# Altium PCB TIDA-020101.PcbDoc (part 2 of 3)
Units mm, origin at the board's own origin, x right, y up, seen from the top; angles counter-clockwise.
Board outline 55 x 55 mm, 4 copper layers (Top Layer 1, Top Layer, Bottom Layer, Bottom Layer 1), stack 1.647 mm thick; 151 components, 88 nets, 395 pads, 362 vias.
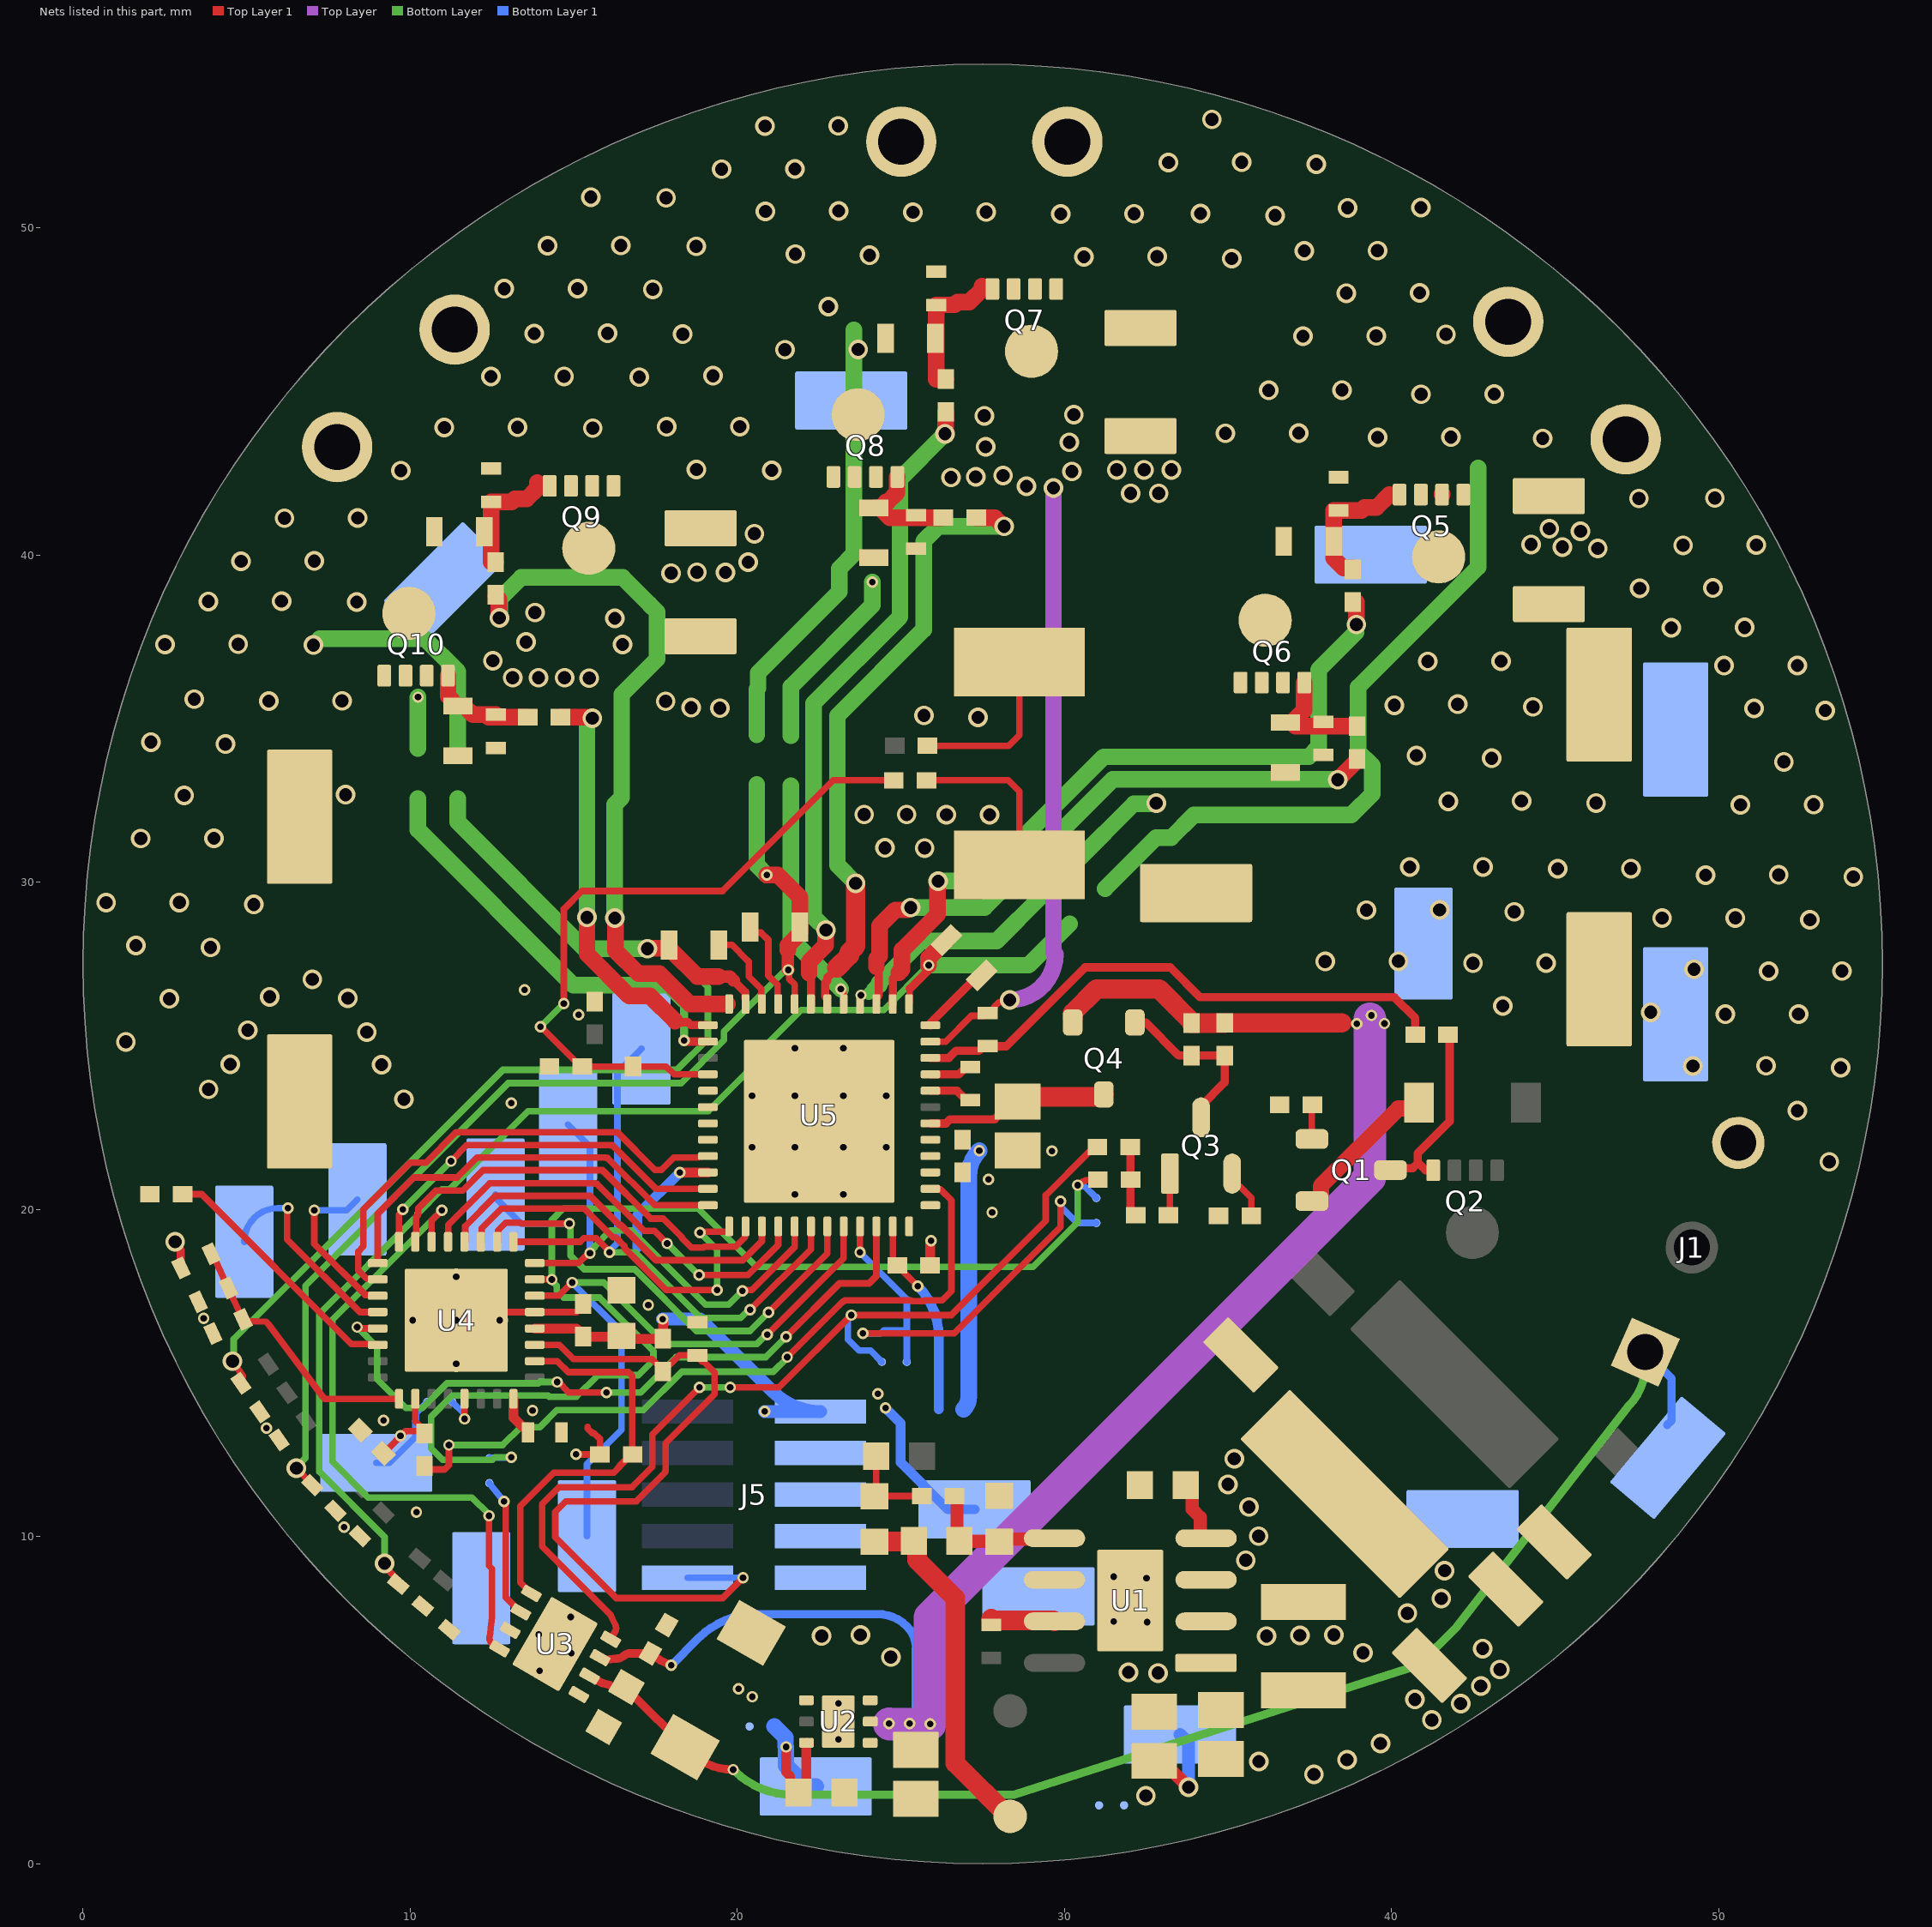
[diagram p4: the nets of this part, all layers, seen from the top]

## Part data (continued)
C13 C15 C22 C25: library part CMP-0080610-1, "CAP, CERM, 0.1 µF, 25 V,+/- 10%, X7R, AEC-Q200 Grade 1, 0402", Cap_Case=0402, Manufacturer=TDK, Supplier Part Number 1=445-6902-1-ND, TempCo=X7R, Tolerance_%=10%, Value2=25V, ValueDisplayed=0.1µF
C14: library part CMP-0007003-5, "CAP, CERM, 10 uF, 10 V, +/- 20%, X5R, 0603", Cap_Case=0603, Manufacturer=TDK, Supplier Part Number 1=445-6853-1-ND, TempCo=X5R, Tolerance_%=20%, Value1="0.0078 ohm", Value2=10V, ValueDisplayed=10uF
C16: library part CMP-0860964-1, "CAP, CERM, 0.47 µF, 16 V,+/- 10%, X7S, 0402", Cap_Case=0402, Manufacturer=TDK, TempCo=X7S, Tolerance_%=10%, Value2=16V, ValueDisplayed=0.47µF
C17 C18 C19 C20 C21: library part CMP-0006639-2, "CAP, CERM, 0.01 uF, 16 V, +/- 10%, X7R, 0402", Cap_Case=0402, Manufacturer=MuRata, Supplier Part Number 1=490-1313-1-ND, TempCo=X7R, Tolerance_%=10%, Value1=Unknown, Value2=16V, ValueDisplayed=0.01uF
C24: library part CMP-0006320-2, "CAP, CERM, 470 pF, 50 V, +/- 10%, X7R, AEC-Q200 Grade 1, 0402", Cap_Case=0402, Manufacturer=TDK, Supplier Part Number 1=445-6888-1-ND, TempCo=X7R, Tolerance_%=10%, Value1="4.96489 ohm", Value2=50V, ValueDisplayed=470pF
C26 C27 C31: library part CMP-0006276-2, "CAP, CERM, 1 uF, 25 V, +/- 10%, X5R, 0402", Cap_Case=0402, Manufacturer=TDK, Supplier Part Number 1=445-9066-1-ND, TempCo=X5R, Tolerance_%=10%, Value1=Unknown, Value2=25V, ValueDisplayed=1uF
C28 C29 C30: library part CMP-0082523-1, "CAP, CERM, 1 µF, 25 V,+/- 10%, X7R, AEC-Q200 Grade 1, 0603", Cap_Case=0603, Manufacturer=TDK, Supplier Part Number 1=445-9819-1-ND, TempCo=X7R, Tolerance_%=10%, Value2=25V, ValueDisplayed=1µF
C32 C33 C35: library part CMP-0127119-1, "130 µF 80 V Aluminum - Polymer Capacitors Radial, Can - SMD 16mOhm 4000 Hrs @ 125°C", Digikey Part Number=495-B40910A0137M000TR-ND, Leakage Current=100uA, Manufacturer=TDK, Mouser Part Number=871-B40910A0137M000, Operating Temperature Range="-55°C to +150°C", Tolerance_%=20%, ValueDisplayed=130uF
C36 C37 C38: library part CMP-0006332-2, "CAP, CERM, 1000 pF, 100 V, +/- 10%, X7S, AEC-Q200 Grade 1, 0402", Cap_Case=0402, Manufacturer=TDK, Supplier Part Number 1=445-6904-1-ND, TempCo=X7S, Tolerance_%=10%, Value1="2.71151 ohm", Value2=100V, ValueDisplayed=1000pF
C40 C41 C43 C44 C46 C47: library part CMP-0007082-4, "CAP, CERM, 0.01 uF, 100 V, +/- 10%, X7R, AEC-Q200 Grade 1, 0603", Cap_Case=0603, Manufacturer=TDK, Supplier Part Number 1=445-5812-1-ND, TempCo=X7R, Tolerance_%=10%, Value1="0.235428 ohm", Value2=100V, ValueDisplayed=0.01uF
D1: library part CMP-0080761-2, "Diode, Switching, 100 V, 0.25 A, AEC-Q101, SOD-123", Manufacturer=Vishay-Semiconductor, Value1=0.25A, Value2=1.25V
D2: library part CMP-0006043-3, "Diode, TVS, Bi, 58.1 V, 121 Vc, AEC-Q101, SMD, 2-Leads, Body 4.275x2.575mm", Manufacturer=STMicroelectronics, Value1=600W
J1: library part CMP-0055340-2, "Terminal Block, 3.5 mm, 3x1, Tin, TH", Manufacturer=Molex, Supplier Part Number 1=WM7878-ND
J2 J3 J4 J6 J7 J8 J9: library part CMP-0080367-2, "Solder Jumper, SMT", Manufacturer=NA
J5: library part CMP-0075634-2, "Header(Shrouded), 1.27mm, 5x2, Gold, SMT", Color=Black, Current_A=3.3A, Manufacturer=Samtec, Supplier Part Number 1=SAM8799-ND
L1: library part CMP-0126669-1, "2.2 µH Shielded Wirewound Inductor 12.4 A 11.9mOhm Max Nonstandard", Digikey Part Number=732-74438377022CT-ND, Manufacturer="Wurth Electronics", Mouser Part Number=710-74438377022, Operating Temperature Range="-40°C to +125°C", Self Resonant Frequency=30MHz, Test Frequency=100kHz, Tolerance_%=20%
L2: library part CMP-0123992-1, "Low Profile Shielded Power Inductors 100uH 20% 0.82A 0.475 Ohm", Manufacturer=Coilcraft, Operating Temperature Range=to, Self Resonant Frequency=8.6MHz, Test Frequency=100kHz, Tolerance_%=20%
Logo1: library part CMP-0074844-1
Logo2 Logo5: library part CMP-0074838-1, "Texas Instrument Corporate Signature"
Logo3: library part CMP-0074847-1, "FCC_disclaimer"
Logo4: library part CMP-0074769-1
Logo6: library part CMP-0074837-2, "IEC 61010-1 Hot Surface Warning", Manufacturer="Texas Instruments"
MH1 MH2 MH3: library part CMP-0089624-1, "0.250\" (6.35mm) Quick Connect Male  Solder Connector Non-Insulated", Current_A=20A, Digikey Part Number=A29938CT-ND, Manufacturer="TE Connectivity", Mouser Part Number=571-638241, Operating Temperature Range="-40°C to +105°C"
NT1 NT2 NT3 NT4 NT5 NT6 NT7: library part CMP-0078142-6, "Single point connection between nets.", Manufacturer=N/A
Q1: library part CMP-0000380-2, "Transistor, NPN, 32 V, 0.1 A, SOT-23", Manufacturer="Infineon Technologies", Supplier Part Number 1="BCW 60D E6327-ND", Value1="0.1 A", Value2=630
Q2 Q5 Q6 Q7 Q8 Q9 Q10: library part CMP-0126680-2, "N-Channel 80 V 11A (Ta), 68A (Tc) 3.2W (Ta), 107W (Tc) Surface Mount 8-WDFN (3.3x3.3)", Digikey Part Number=NVTFS6H850NTAGOSCT-ND, Drain To Source Breakdown Voltage=80V, Input Capacitace At Vds="1140pF @ 40V", Manufacturer=onsemi, Mouser Part Number=863-NVTFS6H850NTAG, Operating Temperature Range="-55°C to +175°C", Power_W=3.2W, Pulse Drain Current=300A, Typ Forward Diode Voltage=0.8V
Q3: library part CMP-0097440-1, "Bipolar (BJT) Transistor NPN 40 V 200 mA 300MHz 300 mW Surface Mount SOT-23-3 (TO-236)", Collector Base Voltage=60V, Digikey Part Number=SMMBT3904LT3GOSCT-ND, Emitter Base Voltage=6V, Manufacturer="On Semiconductor", Mouser Part Number=863-SMMBT3904LT3G, Operating Temperature Range="-55°C to +150°C", Power_W=225mW, Unity Gain Freq=300MHz
Q4: library part CMP-0000155-3, "MOSFET, P-CH, -60 V, -0.185 A, SOT-23", Alternate Manufacturer=None, Manufacturer=Vishay-Siliconix, Value1=1, Value2="1.7 nC"
R1 R10: library part CMP-0026935-3, "RES, 47 k, 5%, 0.063 W, AEC-Q200 Grade 0, 0402", Manufacturer=Vishay-Dale, Power_W=63mW, Supplier Part Number 1=541-47KJCT-ND, TempCo="200 ppm/C", Tolerance_%=5%, Value2=0.063W, Value_Code=47k0, ValueDisplayed=47k
R2 R7 R9 R19 R20 R22: library part CMP-0026825-5, "RES, 10 k, 5%, 0.063 W, AEC-Q200 Grade 0, 0402", Manufacturer=Vishay-Dale, Power_W=63mW, Supplier Part Number 1=541-10KJCT-ND, TempCo="200 ppm/C", Tolerance_%=5%, Value2=0.063W, Value_Code=10k0, ValueDisplayed=10k
R3: library part CMP-0022632-4, "RES, 88.7 k, 1%, 0.1 W, AEC-Q200 Grade 0, 0603", Manufacturer=Vishay-Dale, Power_W=100mW, Supplier Part Number 1=541-88.7KHCT-ND, TempCo="100 ppm/C", Tolerance_%=1%, Value2=0.1W, Value_Code=88k7, ValueDisplayed=88.7k
R4: library part CMP-0025319-2, "RES, 481 k, 0.5%, 0.1 W, 0603", Manufacturer="Yageo America", Power_W=100mW, TempCo="50 ppm/C", Tolerance_%=0.5%, Value2=0.1W, Value_Code=481k
R5: library part CMP-0023120-4, "RES, 453 k, 1%, 0.1 W, 0603", Manufacturer=Yageo, Power_W=100mW, Supplier Part Number 1=311-453KHRCT-ND, TempCo="100 ppm/C", Tolerance_%=1%, Value2=0.1W, Value_Code=453k
R6: library part CMP-0024307-2, "RES, 50.5 k, 0.1%, 0.1 W, 0603", Manufacturer="Yageo America", Power_W=100mW, TempCo="25 ppm/C", Tolerance_%=0.1%, Value2=0.1W, Value_Code=50k5, ValueDisplayed=50.5k
R8: library part CMP-0026938-5, "RES, 4.7 k, 5%, 0.063 W, AEC-Q200 Grade 0, 0402", Manufacturer=Vishay-Dale, Power_W=63mW, Supplier Part Number 1=541-4.7KJCT-ND, TempCo="200 ppm/C", Tolerance_%=5%, Value2=0.063W, Value_Code=4k70, ValueDisplayed=4.7k
R11 R13 R15 R17: library part CMP-0026615-3, "RES, 976 k, 1%, 0.063 W, AEC-Q200 Grade 0, 0402", Manufacturer=Vishay-Dale, Power_W=63mW, Supplier Part Number 1=541-976KLCT-ND, TempCo="100 ppm/C", Tolerance_%=1%, Value2=0.063W, Value_Code=976k
R12 R14 R16 R18: library part CMP-0026284-2, "RES, 30.1 k, 1%, 0.063 W, AEC-Q200 Grade 0, 0402", Manufacturer=Vishay-Dale, Power_W=63mW, Supplier Part Number 1=541-30.1KLCT-ND, TempCo="100 ppm/C", Tolerance_%=1%, Value2=0.063W, Value_Code=30k1, ValueDisplayed=30.1k
R21 R29 R31 R33 R35 R37 R39: library part CMP-0026823-3, "RES, 100 k, 5%, 0.063 W, AEC-Q200 Grade 0, 0402", Manufacturer=Vishay-Dale, Power_W=63mW, Supplier Part Number 1=541-100KJCT-ND, TempCo="200 ppm/C", Tolerance_%=5%, Value2=0.063W, Value_Code=100k
R24: library part CMP-0026845-3, "RES, 160, 5%, 0.063 W, AEC-Q200 Grade 0, 0402", Manufacturer=Vishay-Dale, Power_W=63mW, Supplier Part Number 1=541-160JCT-ND, TempCo="200 ppm/C", Tolerance_%=5%, Value2=0.063W, Value_Code=160R, ValueDisplayed=160
R25: library part CMP-0015751-2, "RES, 0.005, 1%, 3 W, AEC-Q200 Grade 0, 2512", Manufacturer=Bourns, Power_W=3W, Supplier Part Number 1=CRE2512-FZ-R005E-3CT-ND, TempCo="75 ppm/C", Tolerance_%=1%, Value_Code=5L000, ValueDisplayed=0.005
R26 R27: library part CMP-0025963-3, "RES, 10.0, 1%, 0.063 W, AEC-Q200 Grade 0, 0402", Manufacturer=Vishay-Dale, Power_W=63mW, Supplier Part Number 1=541-10.0LCT-ND, TempCo="100 ppm/C", Tolerance_%=1%, Value2=0.063W, Value_Code=10R0, ValueDisplayed=10.0
R28 R30 R32 R34 R36 R38: library part CMP-0026822-3, "RES, 0, 5%, 0.063 W, AEC-Q200 Grade 0, 0402", Manufacturer=Vishay-Dale, Power_W=63mW, Supplier Part Number 1=541-0.0JCT-ND, TempCo="200 ppm/C", Tolerance_%=5%, Value2=0.063W, Value_Code=0000, ValueDisplayed=0
TP1 TP2 TP3 TP4 TP5 TP6 TP7 TP8 TP9 TP10 TP11 TP12 TP13 TP14 TP15 TP16 TP17 TP18 TP19: library part CMP-0078225-3, "PC Test Point, SMT", Manufacturer="Keystone Electronics", Supplier Part Number 1=36-5017CT-ND
U1: library part CMP-0092718-1, "0.3-A,120-V, Step-Down Converter with Fly-buck Capability", Manufacturer="Texas Instruments", Max Supply Voltage=115V, Min Supply Voltage=6V, Nominal Supply Current=10-420uA, Operating Temperature Range="-40°C to +150°C", Switching Frequency=1MHz
U2: library part CMP-0860463-2, "Automotive 150-mA high-voltage ultra-low-IQ low-dropout (LDO) linear regulator, DRV0006A (WSON-6)", Alternate Manufacturer="Texas Instruments", Operating Temperature Range="-40 to 150 C", Rating=Automotive
U3: library part CMP-0126781-1, "Automotive LIN Transceiver with Dominant State Timeout and Extended Fault Protection", Manufacturer="Texas Instruments", Max Supply Voltage=48V, Min Supply Voltage=4V, Nominal Supply Current=1-1.2mA, Operating Temperature Range="-40°C to +125°C"
U4: library part CMP-0120871-1, "Automotive Mixed-Signal Microcontrollers With CAN-FD Interface", Frequency_Fixed=80MHz, Manufacturer="Texas Instruments", Max Supply Voltage=3.6V, Min Supply Voltage=1.62V, Operating Temperature Range="-40°C to +125°C"
U5: library part CMP-0122985-1, "48V Battery Three-Phase Smart Gate Driver with Accurate Current Sensing and Advanced Monitoring", Manufacturer="Texas Instruments", Max Supply Voltage=85V, Min Supply Voltage=8V, Operating Temperature Range="-40°C to +150°C"
ZZ1: library part CMP-0003616-3
ZZ2: library part CMP-0077236-1
ZZ3: library part CMP-0077237-1
ZZ4: library part CMP-0077238-1

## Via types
v1: diameter 0.6, hole 0.4, Top Layer 1 to Bottom Layer 1, tented both sides, 247 vias
v2: diameter 0.35, hole 0.2, Top Layer 1 to Bottom Layer 1, tented both sides, 92 vias
v3: diameter 0.5, hole 0.2, Top Layer 1 to Bottom Layer 1, tented both sides, 21 vias
v4: diameter 0.5, hole 0.2, Top Layer 1 to Bottom Layer 1, tented bottom, 2 vias

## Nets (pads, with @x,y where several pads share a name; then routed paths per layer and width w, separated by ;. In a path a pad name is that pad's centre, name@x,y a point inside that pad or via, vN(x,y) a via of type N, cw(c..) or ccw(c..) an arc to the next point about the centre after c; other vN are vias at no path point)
12V_Buck: C7.1 C8.1 C9.1 J2.1 L2.2 R5.2 TP2.1 | length 14
  Top Layer 1 w0.4: C8.1@32.741,3.143 cw(c32.741,2.562) 33.152,2.973 v1(33.79,2.334)
  Top Layer 1 w0.6: C7.1@24.186,9.834 24.201,9.85 R5.2@25.376,9.85 ; R5.2@25.392,9.865 25.492,9.765 25.492,9.284 26.663,8.112 26.663,3.07 L2.2@28.344,1.389
  Bottom Layer 1 w0.4: TP2.1@33.53,3.948 33.79,3.688 v1(33.79,2.334)
  other v1: 32.487,2.077 35.939,3.121
+3V3: C14.1 C15.1 C25.1 J3.2 J5.1 J9.2 R7.2 R10.2 TP4.1 U4.4 U5.23 | length 24.9
  Top Layer 1 w0.2: v2(15.067,12.512) 15.071,12.508 15.794,12.508 R7.2@15.799,12.503 15.799,12.978 15.624,13.153 15.574,13.153 15.424,13.303 15.424,13.353 ; U5.23@24.75,19.476 24.75,18.424 C25.1@24.892,18.282 ; C25.1@24.889,18.279 24.945,18.279 25.092,18.132 25.092,18.076 v2(25.519,17.648)
  Top Layer 1 w0.3: U4.4@13.807,16.358 15.085,16.358 15.285,16.158 C15.1@15.285,16.108 16.443,16.108 C14.1@16.461,16.126 16.545,16.043 R10.2@17.727,16.043 17.725,16.044 17.725,16.637 v2(17.716,16.646)
  Bottom Layer 1 w0.3: v2(24.527,13.926) 24.989,13.463 24.989,12.269 26.428,10.83 TP4.1@27.253,10.83 ; v2(25.519,17.648) cw(c23.989,16.118) 26.153,16.118 J9.2@26.153,13.885
  Bottom Layer 1 w0.4: v2(17.716,16.646) 18.864,16.646 21.088,14.423 ccw(c22.544,15.879) J5.1@22.544,13.82 v2(20.832,13.82)
  other v2: 20.453,5.101 20.038,5.342 24.295,14.359
+3V3_DRV: C31.1 J9.1 U5.28 | length 8
  Bottom Layer 1 w0.508: J9.1@26.915,13.885 ccw(c26.536,14.264) 27.072,14.264 27.072,21.014 cw(c28.178,21.014) v2(27.396,21.797)
+12V: C10.1 C13.1 C22.1 J2.2 Q4.2 R21.2 U2.1 U2.2 U3.7 | length 50.8
  Top Layer 1 w0.254: U3.7@15.804,6.297 15.968,6.235 16.329,6.269 ccw(c16.293,6.644) 16.545,6.363 cw(c16.713,6.173) 16.713,6.427 C13.1@17.341,6.427 17.644,6.216 v2@17.962,6.065
  Top Layer 1 w0.6: Q4.2@30.254,25.822 30.254,26.008 30.98,26.734 32.89,26.734 33.88,25.744 R21.2@33.88,25.694 33.882,25.696 34.896,25.696 C22.1@34.898,25.698 38.47,25.698
  Top Layer w1: v2(24.64,4.28) 24.655,4.265 v2(25.891,4.265) 25.891,7.53 39.335,20.973 v2@39.335,25.823
  Bottom Layer 1 w0.254: v2(17.98,6.065) 18.799,6.884 cw(c20.596,5.088) 20.596,7.628 24.286,7.628 cw(c24.286,6.365) 25.179,7.258 cw(c24.505,6.584) 25.458,6.584 25.458,4.748 cw(c24.797,4.748) v2(25.264,4.28)
  other v2: 38.935,25.669 39.781,25.677 39.382,25.927
+48V: C3.2 C4.1 C27.2 C32.2 C33.2 C35.2 C39.2 C42.2 C45.2 L1.2 Q5.5-6-7-8 Q7.5-6-7-8 Q9.5-6-7-8 R11.2 TP1.1 U1.2 U1.3 U5.35 | length 20.5
  Top Layer 1 w0.2: U5.35@25.9,25.126 26.367,25.126 27.155,25.914 27.558,25.914 C27.2@27.648,26.005 27.763,26.005 27.853,26.095 27.853,26.187 27.989,26.323 28.247,26.323 v1(28.323,26.399)
  Top Layer 1 w0.254: v1(2.815,19.008) 2.815,18.915 2.986,18.744 2.986,18.229 R11.2@3.081,18.134
  Top Layer w0.508: v1(28.323,26.399) ccw(c28.323,27.795) 29.719,27.795 29.663,27.851 v1(29.663,42.048)
  other v1: 41.228,4.389 42.108,4.895 40.71,5.02 42.725,5.432 43.311,5.935 39.124,6.446 42.782,6.575 36.173,6.956 37.194,6.974 38.233,6.993 40.482,7.654 41.516,8.1 41.619,8.952 35.54,9.274 35.934,10.011 35.638,10.903 34.996,11.594 35.189,12.378 9.807,23.365 3.836,23.666 9.128,24.421 4.499,24.432 8.674,25.415 5.039,25.475 8.095,26.45 5.705,26.495 7.008,27.027 50.663,32.362 52.901,32.369 46.249,32.419 41.731,32.472 43.97,32.479 51.989,33.676 43.058,33.786 40.756,33.868 53.25,35.246 51.075,35.31 44.319,35.356 40.082,35.407 42.017,35.438 13.131,36.247 13.924,36.247 14.717,36.247 15.472,36.235 50.163,36.618 52.402,36.625 41.105,36.745 43.344,36.752 12.525,36.767 16.491,37.263 13.54,37.339 16.253,38.064 13.812,38.241 17.975,39.444 18.764,39.474 19.635,39.465 20.332,39.777 20.52,40.649 28.839,42.103 26.532,42.368 27.286,42.39 28.122,42.428 30.229,42.553 27.587,43.304 30.146,43.444 27.548,44.253 30.285,44.288
AGND: C10.2 C11.2 C12.2 C13.2 C14.2 C15.2 C16.1 C17.2 C18.2 C19.2 C20.2 C21.2 C24.2 D2.1 J5.3 J5.5 J5.7 J5.9 NT1.1 R9.1 R12.1 R14.1 R16.1 R18.1 TP19.1 U2.3 U2.4 U2.7@23.086,4.344 U3.3 U3.5 U3.9 U4.5 U4.33 U5.10 | length 6.5
  Top Layer 1 w0.2: v3(12.737,16.608) cw(c12.987,16.608) 12.987,16.858 U4.5@13.807,16.858 15.085,16.858 15.285,17.058 C15.2@15.285,17.108
  Top Layer 1 w0.3: v2(18.24,21.126) U5.10@19.1,21.126
  Bottom Layer 1 w0.3: 16.945,18.83 16.945,19.831 v2(18.24,21.126)
  other v1: 24.692,6.315 22.575,6.959 23.761,6.987
  other v2: 7.974,10.283 10.189,10.741 5.603,13.313 9.181,13.551 13.738,13.852 3.688,16.672 17.277,17.078
  other v3: 13.954,5.893 14.927,6.428 13.931,7.003 14.904,7.538 11.407,15.278 10.077,16.608 11.407,16.608 11.407,17.938
  other v4: 23.086,3.794 23.086,4.894
BSL_Invoke: R9.2 U4.22 | length 7.9
  Top Layer 1 w0.2: R9.2@3.042,20.462 3.627,20.462 8.206,15.883 8.982,15.883 U4.22@9.007,15.858
BSTA: C28.1 U5.36 | length 2.2
  Top Layer 1 w0.254: U5.36@25.9,25.626 25.9,25.688 27.366,27.153 C28.1@27.471,27.153
BSTB: C29.1 U5.45 | length 2.8
  Top Layer 1 w0.2: C29.1@20.388,28.622 20.388,28.61 20.542,28.456 20.725,28.456 20.947,28.234 20.947,27.145 21.23,26.862 21.23,26.296 U5.45@21.25,26.276
BSTC: C30.1 U5.46 | length 2.6
  Top Layer 1 w0.2: C30.1@19.435,28.081 19.838,28.081 20.304,27.614 20.353,27.565 cw(c19.577,27.532) 20.354,27.532 20.354,27.11 20.73,26.734 20.73,26.476 20.75,26.456 U5.46@20.75,26.276
CPTH: C26.1 U5.33 | length 1.3
  Top Layer 1 w0.254: U5.33@25.9,24.126 26.775,24.126 27.003,24.354 C26.1@27.117,24.354
CPTL: C26.2 U5.32 | length 1.3
  Top Layer 1 w0.254: U5.32@25.9,23.626 26.715,23.626 27.003,23.338 C26.2@27.117,23.338
DAC_OUT: TP6.1 U4.19 | length 5.1
  Top Layer 1 w0.2: v2(7.067,19.971) 7.067,18.945 8.628,17.383 8.982,17.383 U4.19@9.007,17.358
  Bottom Layer 1 w0.2: v2(7.067,19.971) 8.056,19.971 TP6.1@8.387,20.302
DRV_DRVOFF: U4.18 U5.9 | length 14.8
  Top Layer 1 w0.2: U4.18@9.007,17.858 8.982,17.883 8.662,17.883 8.407,18.138 8.407,18.704 8.572,18.869 8.572,20.001 10,21.429 10.481,21.429 11.404,22.352 16.334,22.352 17.485,21.201 17.675,21.201 18.052,21.579 18.804,21.579 18.831,21.606 18.9,21.606 18.92,21.626 U5.9@19.1,21.626
DRV_GVDD: C23.1 Q4.3 U5.30 | length 5.5
  Top Layer 1 w0.254: U5.30@25.9,22.626 26.376,22.626 26.503,22.753 27.871,22.753 C23.1@28.416,23.298
  Top Layer 1 w0.4: C23.1@28.566,23.298 C23.1@28.701,23.433
  Top Layer 1 w0.6: C23.1@28.701,23.433 31.123,23.433 Q4.3@31.202,23.513
DRV_GVDD_SW: R8.2 R19.1 R20.2 | length 2.4
  Top Layer 1 w0.254: R20.2@32.006,19.941 32.129,19.818 R20.2@32.175,19.818 32.017,19.941 32.017,21.785 R19.1@32.007,21.908
DRV_nFAULT: U4.21 U5.22 | length 21.6
  Top Layer 1 w0.2: v2(8.38,16.4) ccw(c8.421,16.4) 8.421,16.358 U4.21@9.007,16.358 ; v2(14.49,14.723) 14.531,14.723 14.85,14.403 v2(16.003,14.403) ; v2(21.494,16.107) 23.123,17.736 24.027,17.736 24.25,17.959 U5.22@24.25,19.476
  Bottom Layer w0.2: v2(8.38,16.4) 8.984,15.795 8.984,14.812 9.869,13.927 10.372,13.927 11.127,14.682 13.915,14.682 13.956,14.723 v2(14.49,14.723) ; v2(16.003,14.403) 17.043,14.403 18.12,15.48 20.867,15.48 v2(21.494,16.107)
DRV_nSCS: TP11.1 U4.6 U5.20 | length 21.3
  Top Layer 1 w0.2: U4.6@13.807,17.358 14.547,17.358 14.9,17.712 v2(14.949,17.761) ; v2(20.911,16.168) 20.915,16.168 23.25,18.504 U5.20@23.25,19.476
  Bottom Layer w0.2: v2(14.949,17.761) 15.916,17.761 17.797,15.88 20.594,15.88 20.881,16.168 v2(20.911,16.168)
  Bottom Layer 1 w0.2: v2(14.949,17.761) 16.456,16.255 16.456,13.261 15.403,12.208 TP11.1@15.403,10.01
DRV_nSLEEP: J6.2 J8.2 U5.21 | length 15.7
  Top Layer 1 w0.2: v2(23.75,18.691) U5.21@23.75,19.476 ; v2(23.835,16.211) 26.63,16.211 29.88,19.461 v2(29.88,20.247)
  Bottom Layer 1 w0.2: v2(23.75,18.691) 25.179,17.262 25.179,16.3 ; v2(23.835,16.211) 24.39,16.211 24.478,16.3 25.179,16.3 ; J8.2@25.179,15.338 25.179,16.3 ; v2(29.88,20.247) 29.909,20.219 29.909,20.064 30.39,19.583 J6.2@30.973,19.583
DRV_SCLK: TP8.1 U4.10 U5.19 | length 16.9
  Top Layer 1 w0.2: U4.10@12.657,19.008 12.682,19.033 12.682,19.353 12.915,19.586 13.368,19.586 13.387,19.567 v2(14.867,19.567) ; v2(20.956,16.85) 20.956,16.854 22.753,18.65 22.753,19.473 U5.19@22.75,19.476
  Bottom Layer w0.2: v2(14.867,19.567) 14.896,19.538 14.896,18.588 15.315,18.169 16.859,18.169 18.748,16.28 20.383,16.28 20.66,16.558 20.667,16.558 20.956,16.848 v2(20.956,16.85)
  Bottom Layer 1 w0.2: TP8.1@12.607,20.452 12.607,20.357 13.397,19.567 v2(14.867,19.567)
DRV_SDI: TP9.1 U4.9 U5.18 | length 18.3
  Top Layer 1 w0.2: U4.9@13.157,19.008 15.2,19.008 15.309,19.117 15.684,19.117 16.094,18.707 v2(16.094,18.687) ; v2(20.391,16.927) v2(20.391,16.927) 22.247,18.782 22.247,19.473 U5.18@22.25,19.476
  Bottom Layer w0.2: v2(16.094,18.687) 16.875,18.687 18.882,16.68 20.104,16.68 20.35,16.927 v2(20.391,16.927)
  Bottom Layer 1 w0.2: v2(16.094,18.687) 16.094,18.728 16.332,18.966 16.332,24.173 TP9.1@17.069,24.91
DRV_SDO: TP10.1 U4.8 U5.17 | length 14.9
  Top Layer 1 w0.2: U4.8@13.807,18.358 15.15,18.358 15.456,18.664 v2(15.496,18.664) ; v2(20.155,17.509) 20.184,17.538 20.438,17.538 21.75,18.85 U5.17@21.75,19.476
  Bottom Layer w0.2: v2(15.496,18.664) 15.496,18.705 15.641,18.85 15.641,18.875 16.12,19.353 16.761,19.353 19.032,17.083 19.73,17.083 v2(20.155,17.509)
  Bottom Layer 1 w0.2: TP10.1@14.822,22.589 15.496,21.915 v2(15.496,18.664)
DRV_VCP: C27.1 R2.2 U5.34 | length 16.9
  Top Layer 1 w0.254: U5.34@25.9,24.626 26.463,24.626 26.686,24.849 27.39,24.849 C27.1@27.444,24.903 ; C27.1@27.648,24.989 27.652,24.985 28.22,24.985 30.629,27.394 33.234,27.394 34.146,26.482 40.085,26.482 40.721,25.847 R2.2@40.721,25.34
FAULT_OUT: TP7.1 U4.20 | length 6.6
  Top Layer 1 w0.2: v2(6.259,20.037) 6.238,20.016 6.238,19.084 8.463,16.858 U4.20@9.007,16.858
  Bottom Layer 1 w0.2: TP7.1@4.927,19.009 cw(c5.956,19.009) 5.956,20.037 v2(6.259,20.037)
FB: C6.1 R5.1 R6.2 U1.5 | length 4.4
  Top Layer 1 w0.4: C6.1@26.635,11.235 26.663,11.235 26.713,11.185 26.713,9.943 R5.1@26.792,9.865 26.803,9.854 27.998,9.854 R6.2@28.01,9.842 28.088,9.92 29.667,9.92 U1.5@29.694,9.947
GHA: R28.1 U5.38 | length 22.7
  Top Layer 1 w0.254: U5.38@24.75,26.276 24.754,26.28 24.754,27.054 24.935,27.235
  Top Layer 1 w0.508: 24.935,27.235 25.032,27.331 25.032,27.922 26.122,29.013 26.122,30.014 v1(26.14,30.031) ; R28.1@38.809,38.558 38.921,38.558 v1(38.921,37.874)
  Bottom Layer w0.508: v1(26.14,30.031) 27.396,30.031 31.196,33.831 37.467,33.831 37.765,34.128 37.765,36.491 38.904,37.63 38.904,37.856 v1(38.921,37.874)
GHB: R32.1 U5.43 | length 20.2
  Top Layer 1 w0.254: 22.191,27.222 22.25,27.163 U5.43@22.25,26.276
  Top Layer 1 w0.508: 22.191,27.222 22.191,27.563 22.693,28.065 22.693,28.516 v1(22.71,28.533) ; v1(26.35,43.704) 26.35,43.729 26.368,43.747 26.368,44.369 R32.1@26.372,44.373
  Bottom Layer w0.508: v1(22.71,28.533) 22.71,28.558 22.325,28.943 22.325,35.461 24.97,38.106 24.97,42.324 v1(26.35,43.704)
GHC: R36.1 U5.48 | length 21.8
  Top Layer 1 w0.508: R36.1@12.619,38.735 12.707,38.647 12.707,38.095 v1(12.725,38.078) ; v1(16.253,28.9) 16.271,28.882 16.271,27.91 16.976,27.205 17.619,27.205 18.548,26.276 U5.48@19.698,26.276
  Bottom Layer w0.508: v1(12.725,38.078) 12.742,38.095 12.742,38.661 13.395,39.314 16.493,39.314 17.307,38.501 17.307,38.497 17.545,38.259 17.545,36.817 16.466,35.738 16.466,32.588 16.253,32.375 v1(16.253,28.9)
GLA: R30.1 U5.39 | length 19.2
  Top Layer 1 w0.2: 24.248,27.413 24.248,27.334 24.275,27.307 ; U5.39@24.25,26.276 24.27,26.296 24.27,26.476 24.3,26.506 U5.39@24.3,26.525
  Top Layer 1 w0.254: 24.275,27.307 24.323,27.26 24.323,26.547 U5.39@24.3,26.525
  Top Layer 1 w0.508: 24.248,27.413 24.248,27.647 24.346,27.745 24.346,28.666 24.83,29.151 25.2,29.151 25.273,29.223 v1(25.298,29.223) ; v1(38.352,33.128) 38.935,33.712 38.935,33.762 R30.1@38.939,33.766
  Bottom Layer w0.508: v1(25.298,29.223) 27.558,29.223 31.48,33.145 38.335,33.145 v1(38.352,33.128)
GLB: R34.1 U5.42 | length 19.3
  Top Layer 1 w0.254: U5.42@22.743,26.449 22.683,26.509 22.683,26.924 22.75,26.991 22.75,27.087 23.041,27.378
  Top Layer 1 w0.508: R34.1@27.299,41.138 27.303,41.134 27.875,41.134 28.133,40.876 v1(28.158,40.876)
  Top Layer 1 w0.6: 23.041,27.378 23.425,27.761 23.425,27.858 23.614,28.048 v1(23.614,29.967)
  Bottom Layer w0.508: v1(23.614,29.967) 23.057,30.523 23.057,35.082 25.694,37.719 25.694,40.424 26.146,40.876 v1(28.158,40.876)
GLC: R38.1 U5.1 | length 12.9
  Top Layer 1 w0.254: 18.1,25.749 18.131,25.717 18.489,25.717 18.573,25.633 19.093,25.633 U5.1@19.1,25.626
  Top Layer 1 w0.508: R38.1@14.59,35.043 14.594,35.039 15.512,35.039 15.543,35.008 v1(15.568,35.008) ; v1(15.403,28.924) 15.403,27.807 16.692,26.519 17.329,26.519 18.1,25.749
  Bottom Layer w0.508: v1(15.403,28.924) 15.403,34.818 15.568,34.983 v1(15.568,35.008)
GND: C1.1 C2.1 C3.1 C4.2 C8.2 C9.2 C23.2 C25.2 C31.2 C32.1 C33.1 C35.1 C36.2 C38.2 C39.1 C42.1 C45.1 J1.3 NT1.2 R1.1 R3.1 R6.1 R22.2 R25.1 R27.1 TP16.1 TP17.1 TP18.1 U1.1 U1.6 U1.9 U5.5 U5.6 U5.7 U5.8 U5.27 U5.29 U5.49 | length 6
  Top Layer 1 w0.2: R27.1@25.78,33.112 28.28,33.112 28.618,32.774 R25.1@28.618,30.526
  Top Layer 1 w0.3: C25.2@25.892,18.282 25.892,18.976 cw(c25.985,18.976) v2(25.919,19.042)
  other v1: 37.624,2.733 38.636,3.174 39.658,3.674 32.863,5.828 31.957,5.849 53.377,21.451 52.4,23.014 53.726,24.328 49.208,24.381 51.447,24.388 1.309,25.119 50.198,25.962 52.436,25.969 47.918,26.022 43.397,26.215 2.635,26.433 51.524,27.277 53.763,27.284 49.245,27.337 42.485,27.522 44.724,27.529 37.967,27.575 40.206,27.582 3.896,28.004 1.617,28.064 52.785,28.847 48.267,28.9 50.506,28.907 43.746,29.092 39.228,29.145 41.467,29.152 5.223,29.318 0.705,29.371 2.943,29.378 54.112,30.161 49.594,30.215 51.832,30.222 45.073,30.407 47.311,30.414 40.555,30.46 42.793,30.467 24.509,31.048 25.725,31.043 1.764,31.335 4.003,31.342 25.174,32.067 26.39,32.063 27.708,32.063 23.875,32.068 3.091,32.649 8.023,32.674 4.352,34.219 2.072,34.279 27.358,35.035 25.705,35.094 18.591,35.332 19.466,35.319 5.678,35.534 7.917,35.541 17.807,35.528 3.399,35.594 46.3,40.197 45.219,40.243 44.263,40.322 45.774,40.725 44.818,40.804 32.019,41.882 32.88,41.882 31.597,42.603 32.433,42.603 33.269,42.603
  other v2: 32.528,7.383 31.507,7.407 32.508,8.728 31.507,8.77 27.787,19.904 27.679,20.912 29.62,21.784 13.092,23.25 15.143,25.943 13.493,26.703
  other v3: 21.76,20.452 23.24,20.452 20.45,21.902 21.76,21.902 23.24,21.902 24.55,21.902 20.45,23.474 21.76,23.474 23.24,23.474 24.55,23.474 21.76,24.924 23.24,24.924
GND_bridge: C41.2 C44.2 C47.2 NT3.2 NT5.2 NT7.2 Q6.1 Q6.2 Q6.3 Q8.1 Q8.2 Q8.3 Q10.1 Q10.2 Q10.3 R25.2 R26.1 R31.1 R35.1 R39.1 | length 15.6
  Top Layer 1 w0.2: R26.1@25.811,34.166 28.288,34.166 28.618,34.495 R25.2@28.618,36.726
  Bottom Layer w0.508: NT7.2@10.237,34.081 10.237,35.651 v2(10.24,35.654) ; NT5.2@21.639,34.474 21.639,35.975 24.123,38.458 v2(24.123,39.166) ; NT3.2@30.381,30.656 32.121,32.395 32.786,32.395 v1(32.804,32.413)
INHA: U4.16 U5.11 | length 11.7
  Top Layer 1 w0.2: U4.16@9.657,19.008 9.657,19.84 9.773,19.956 v2(9.773,19.996) ; v2(11.25,21.473) 11.25,21.477 11.731,21.958 16.132,21.958 16.134,21.956 16.183,21.956 17.513,20.626 U5.11@19.1,20.626
  Bottom Layer w0.2: v2(9.773,19.996) v2(11.25,21.473)
INHB: U4.11 U5.13 | length 12
  Top Layer 1 w0.2: U4.11@12.157,19.008 12.182,19.033 12.182,19.419 12.79,20.026 14.775,20.026 14.781,20.02 15.315,20.02 16.195,19.14 16.282,19.14 16.547,18.875 16.547,18.811 17.825,17.533 19.377,17.533 v2(19.38,17.536) ; v2(18.856,19.289) 18.884,19.318 19.73,19.318 19.75,19.338 U5.13@19.75,19.476
  Bottom Layer w0.2: v2(18.856,19.289) 19.38,18.765 v2(19.38,17.536)
INHC: U4.12 U5.15 | length 11.4
  Top Layer 1 w0.2: U4.12@11.657,19.008 11.682,19.033 11.682,19.487 12.605,20.41 15.502,20.41 16.394,19.518 16.438,19.518 17.513,18.443 20.169,18.443 20.75,19.025 U5.15@20.75,19.476
INLA: U4.17 U5.12 | length 12.9
  Top Layer 1 w0.2: U4.17@9.007,18.358 9.007,19.87 10.111,20.975 11.439,20.975 12.042,21.578 15.989,21.578 15.993,21.573 16.031,21.573 17.479,20.126 U5.12@19.1,20.126
INLB: U4.15 U5.14 | length 13
  Top Layer 1 w0.2: U4.15@10.157,19.008 10.182,19.033 10.182,19.773 10.245,19.836 10.245,20.03 10.79,20.575 11.605,20.575 12.226,21.196 15.875,21.196 17.354,19.716 17.731,19.716 18.305,19.142 18.305,19.119 18.591,18.834 18.966,18.834 18.989,18.856 19.945,18.856 20.23,19.141 20.23,19.456 U5.14@20.25,19.476
INLC: U4.13 U5.16 | length 13.2
  Top Layer 1 w0.2: U4.13@11.157,19.008 U4.13@11.157,19.008 11.159,19.523 12.43,20.793 15.617,20.793 15.622,20.788 15.703,20.788 17.152,19.339 17.468,19.339 v2(17.853,18.954) ; v2(18.827,17.991) 18.829,17.993 20.328,17.993 21.25,18.916 U5.16@21.25,19.476
  Bottom Layer w0.2: v2(17.853,18.954) 17.858,18.954 18.822,17.991 v2(18.827,17.991)
ISENA: C24.1 J4.2 R24.1 TP12.1 U4.26 | length 5.3
  Top Layer 1 w0.2: C24.1@9.181,12.54 9.86,13.219 10.35,13.219 10.407,13.277 10.157,13.527 U4.26@10.157,14.208
  Bottom Layer 1 w0.2: TP12.1@8.962,12.252 9.365,12.252 10.155,13.042 10.155,13.538 10.174,13.557 10.174,13.767 J4.2@10.524,14.117
  other v2: 9.701,13.077
"ISENA (backup)": J4.1 U4.29 | length 1.3
  Top Layer 1 w0.2: U4.29@11.657,14.208 11.661,14.204 11.661,13.598 v2(11.665,13.594)
  Bottom Layer 1 w0.2: J4.1@11.286,14.117 11.636,13.766 11.636,13.622 v2(11.665,13.594)
LIN: C12.1 D2.2 J1.1 TP5.1 U3.6 | length 41.6
  Top Layer 1 w0.254: U3.6@15.479,5.734 15.82,5.544 ; 15.821,5.543 ccw(c15.944,5.766) 15.875,5.521 16.087,5.461 ; 16.088,5.461 cw(c16.018,5.217) 16.145,5.437 16.256,5.373 C12.1@16.612,5.395 ; C12.1@16.772,5.199 D2.2@18.406,3.565 18.546,3.425 ccw(c19.874,4.753) v2(19.874,2.875)
  Bottom Layer w0.254: v2(19.874,2.875) 19.9,2.848 ccw(c21.696,4.644) 21.696,2.104 28.459,2.104 40.815,6.065 41.387,6.637 41.989,7.239 ccw(c41.809,7.418) 42.01,7.262 47.25,14 ccw(c46.039,15.211) 47.752,15.211 J1.1@47.752,15.634
  Bottom Layer 1 w0.254: J1.1@47.752,15.634 48.555,14.83 48.555,13.543 TP5.1@48.422,13.41
LIN_DRV_EN: J6.1 J7.1 R8.1 U4.7 | length 38.6
  Top Layer 1 w0.2: U4.7@13.807,17.858 13.809,17.857 14.327,17.857 v2(14.328,17.855) ; v2(30.401,20.737) cw(c30.825,20.313) 30.825,20.913 R8.1@31.019,20.913
  Bottom Layer w0.2: v2(13.091,12.418) 12.591,12.418 12.516,12.343 10.997,12.343 10.64,12.7 10.64,13.66 11.284,14.304 14.213,14.304 14.247,14.27 15.074,14.27 15.734,14.93 16.968,14.93 17.436,15.398 17.436,15.655 15.789,17.302 14.744,17.302 14.741,17.305 14.689,17.305 14.48,17.513 14.48,17.662 14.328,17.814 14.328,19.668 14.68,20.02 18.803,20.02 20.585,18.238 29.039,18.238 30.401,19.6 v2(30.401,20.737)
  Bottom Layer 1 w0.2: J7.1@12.42,12.395 12.431,12.405 13.078,12.405 v2(13.091,12.418) ; v2(30.401,20.737) 30.43,20.708 30.61,20.708 J6.1@30.973,20.345
LIN_EN: J7.2 U3.2 | length 4.3
  Top Layer 1 w0.2: v2(12.865,11.073) 12.865,11.046 12.924,10.987 12.924,8.143 13.37,7.697 U3.2@13.379,7.697
  Bottom Layer 1 w0.2: J7.2@12.42,11.633 v2(12.865,11.073)
LIN_INH: J8.1 R19.2 U3.8 | length 29.7
  Top Layer 1 w0.2: U3.8@16.129,6.86 16.267,7.101 ccw(c16.093,7.2) 16.274,7.285 16.129,7.594 14.032,9.691 14.032,10.995 14.546,11.508 16.778,11.508 17.399,12.129 17.399,13.12 v2(18.84,14.561) ; v2(19.779,14.558) 19.784,14.553 21.268,14.553 v2(23.481,16.767) 26.542,16.767 29.427,19.652 29.427,20.435 30.75,21.758 30.857,21.758 R19.2@31.007,21.908
  Bottom Layer w0.2: v2(18.84,14.561) 18.841,14.56 v2(19.779,14.558) v2(19.779,14.558)
  Bottom Layer 1 w0.2: v2(23.481,16.767) 23.481,16.726 23.382,16.627 23.382,16.024 23.72,15.686 24.068,15.686 J8.1@24.417,15.338
LIN_RXD: R7.1 U3.1 U4.2 | length 12.4
  Top Layer 1 w0.2: U3.1@13.704,8.26 13.37,8.595 13.37,10.928 14.392,11.95 16.22,11.95 16.399,12.129 16.399,12.153 R7.1@16.749,12.503 ; U4.2@13.807,15.358 14.495,15.358 14.83,15.023 16.671,15.023 16.788,14.906 R7.1@16.788,12.503
LIN_TXD: U3.4 U4.14 | length 20
  Top Layer 1 w0.2: U4.14@10.657,19.008 10.657,19.651 10.965,19.959 v2(10.965,19.969) ; v2(12.407,10.634) 12.407,9.107 12.502,9.012 12.502,7.525 12.46,7.211 ccw(c12.785,7.168) 12.459,7.194 12.447,7.045 cw(c12.247,7.061) 12.444,7.027 12.426,6.921 ccw(c12.624,6.888) 12.449,6.791 ; 12.449,6.79 12.457,6.776 ccw(c12.632,6.874) U3.4@12.522,6.706 ; U3.4@12.729,6.571 U3.4@12.522,6.706 ; U3.4@12.522,6.706 12.563,6.683 U3.4@12.522,6.706
  Bottom Layer w0.2: v2(10.965,19.969) 7.622,16.626 7.622,12.287 8.714,11.194 11.888,11.194 12.407,10.675 v2(12.407,10.634)
M0_nRST: C17.1 J5.10 R10.1 U4.3 | length 23.1
  Top Layer 1 w0.2: U4.3@13.807,15.858 14.561,15.858 14.993,15.426 17.393,15.426 R10.1@17.727,15.093 ; R10.1@17.727,15.043 R10.1@17.727,15.093 ; v2@20.154,8.759 v2(20.173,8.74) 19.55,8.117 16.298,8.117 14.432,9.983 14.432,10.749 14.756,11.073 16.909,11.073 17.799,11.963 17.799,11.995 17.813,12.009 17.813,12.857 19.299,14.343 19.299,15.021 18.977,15.343 18.927,15.343 18.777,15.493 18.777,15.543 18.227,15.543 17.927,15.243 17.877,15.243 R10.1@17.727,15.093
  Bottom Layer 1 w0.2: J5.10@18.474,8.74 v2(20.173,8.74)
MOTA: C40.2 MH1.1 NT2.2 Q5.1 Q5.2 Q5.3 Q6.5-6-7-8 R29.1 TP13.1 | length 21
  Top Layer 1 w0.508: Q5.2@41.535,41.868 41.54,41.863 Q5.2@41.54,41.846
  Bottom Layer w0.508: NT2.2@31.238,29.801 32.796,31.359 33.259,31.359 33.951,32.051 38.765,32.051 38.788,32.074 39.406,32.691 39.406,33.565 38.974,33.996 38.974,35.961 42.643,39.629 42.643,42.654
  other v1: 48.55,37.777 50.789,37.784 47.582,38.982 49.82,38.989 48.908,40.296 51.147,40.303 47.558,41.726 49.878,41.74 44.617,43.562 39.572,43.597 41.811,43.604 34.918,43.718 37.157,43.725 40.899,44.912 43.137,44.918 36.245,45.032 38.483,45.039 37.288,46.688 39.527,46.695 41.662,46.743 38.615,48.002 40.853,48.009 37.328,49.295 39.567,49.302 38.655,50.61 40.893,50.617
MOTB: C43.2 MH2.1 NT4.2 Q7.1 Q7.2 Q7.3 Q8.5-6-7-8 R33.1 TP14.1 | length 13.6
  Bottom Layer w0.508: NT4.2@20.593,34.508 20.593,35.898 20.631,35.937 20.631,36.392 23.115,38.876 23.115,39.584 23.56,40.029 23.56,46.884
  other v1: 21.453,46.276 23.692,46.283 22.78,47.59 35.11,49.06 30.592,49.113 32.831,49.12 24.041,49.16 21.771,49.196 36.437,50.375 29.885,50.421 32.124,50.428 34.157,50.435 25.367,50.475 27.606,50.482 20.858,50.504 23.097,50.511 19.519,51.793 21.757,51.8 37.698,51.945 33.18,51.998 35.419,52.005 20.845,53.107 23.084,53.114 34.506,53.312
MOTC: C46.2 MH3.1 NT6.2 Q9.1 Q9.2 Q9.3 Q10.5-6-7-8 R37.1 TP15.1 | length 7
  Bottom Layer w0.508: v1@7.228,37.442 10.449,37.442 11.455,36.436 NT6.2@11.455,34.081
  other v1: 7.041,37.247 2.502,37.265 4.741,37.272 8.368,38.561 3.828,38.579 6.067,38.586 4.831,39.809 7.07,39.816 6.158,41.123 8.396,41.13 9.716,42.58 21.05,42.584 18.749,42.609 15.581,43.876 11.042,43.894 13.281,43.901 17.837,43.917 20.076,43.924 12.465,45.452 17.004,45.434 14.703,45.459 19.255,45.478 13.791,46.767 16.03,46.774 18.33,46.749 17.415,48.12 12.876,48.138 15.114,48.145 18.741,49.434 14.202,49.452 16.441,49.459 17.821,50.913 15.521,50.938
NetC5_2: C5.2 U1.7 | length 2
  Top Layer 1 w0.6: 27.76,7.492 27.818,7.434 29.667,7.434 U1.7@29.694,7.407
NetC6_2: C6.2 C7.2 R4.2 | length 2.7
  Top Layer 1 w0.2: C7.2@24.186,11.234 C7.2@24.186,11.234 ; R4.2@24.242,12.455 24.242,11.29 C7.2@24.186,11.234 ; C6.2@25.635,11.235 C7.2@24.186,11.234
NetC11_1: C11.1 J3.1 TP3.1 U2.6 | length 5.7
  Top Layer 1 w0.3: v2(21.488,3.57) 21.488,2.799 21.616,2.671 21.616,2.426 C11.1@21.869,2.172 22.111,2.413 U2.6@22.111,3.694
  Bottom Layer 1 w0.5: J3.1@21.135,4.195 21.468,3.861 21.468,3.589 v2(21.488,3.57) 21.488,2.999 22.128,2.359 TP3.1@22.395,2.359
NetC16_2: C16.2 U4.32 | length 1.3
  Top Layer 1 w0.3: U4.32@13.157,14.208 13.157,13.631 13.45,13.338 13.564,13.338 13.605,13.298 C16.2@13.605,13.183
NetC22_2: C22.2 Q3.3 Q4.1 R21.1 | length 5.4
  Top Layer 1 w0.254: Q4.1@32.152,25.713 32.481,25.713 33.496,24.698 C22.2@34.898,24.698 34.898,23.879 34.173,23.155 Q3.3@34.173,22.811
NetC40_1: C40.1 Q5.4 R28.2 R29.2 | length 4.1
  Top Layer 1 w0.508: R28.2@38.809,39.558 38.809,39.6 38.805,39.604 38.525,39.604 38.224,39.905 C40.1@38.224,40.416 38.224,41.359 R29.2@38.377,41.359 39.083,41.359 39.173,41.45 39.538,41.45 39.926,41.838 39.926,41.844
NetC41_1: C41.1 Q6.4 R30.2 R31.2 | length 3.6
  Top Layer 1 w0.508: C41.1@36.753,34.878 C41.1@36.944,34.878 ; Q6.4@37.33,36.101 37.322,36.093 37.322,35.257 C41.1@36.944,34.878 ; R30.2@38.939,34.766 37.056,34.766 C41.1@36.944,34.878
NetC43_1: C43.1 Q7.4 R32.2 R33.2 | length 4.3
  Top Layer 1 w0.508: R32.2@26.372,45.373 26.075,45.373 R33.2@26.075,47.642 26.639,47.642 26.729,47.732 27.094,47.732 27.483,48.121 27.483,48.212
NetC44_1: C44.1 Q8.4 R34.2 R35.2 | length 3.4
  Top Layer 1 w0.508: C44.1@24.169,41.438 C44.1@24.359,41.438 ; Q8.4@24.887,42.384 24.878,42.376 24.878,41.905 24.596,41.622 24.544,41.622 C44.1@24.359,41.438 ; R34.2@26.249,41.138 24.659,41.138 C44.1@24.359,41.438
NetC46_1: C46.1 Q9.4 R36.2 R37.2 | length 3.7
  Top Layer 1 w0.508: R36.2@12.615,39.781 12.477,39.781 R37.2@12.477,41.624 13.105,41.624 13.196,41.715 13.561,41.715 13.884,42.038 13.884,42.217
NetC47_1: C47.1 Q10.4 R38.2 R39.2 | length 3.6
  Top Layer 1 w0.508: Q10.4@11.157,36.312 11.157,35.686 11.269,35.573 11.269,35.383 11.65,35.383 11.916,35.117 R39.2@12.615,35.117 ; R39.2@12.394,35.043 R38.2@13.59,35.043
NetD1_2: D1.2 Q1.2 | length 4.8
  Top Layer 1 w0.5: Q1.2@37.562,20.251 37.64,20.251 37.836,20.447 37.836,20.714 40.202,23.08 40.479,23.08 40.837,23.437 D1.2@40.837,23.537
NetQ1_1: Q1.1 R1.2 | length 1.1
  Top Layer 1 w0.2: Q1.1@37.562,22.151 37.562,23.182 R1.2@37.576,23.196
NetQ1_3: Q1.3 Q2.4 R2.1 | length 5.8
  Top Layer 1 w0.254: Q1.3@39.962,21.201 40.018,21.257 40.65,21.257 40.799,21.405 ; Q2.4@41.271,21.193 41.038,21.193 40.825,21.405 40.799,21.405 ; R2.1@41.721,25.34 41.771,25.29 41.771,22.686 40.799,21.714 40.799,21.405
NetQ3_1: Q3.1 R20.1 | length 1.3
  Top Layer 1 w0.2: R20.1@33.175,19.818 33.223,19.867 Q3.1@33.223,21.091
NetQ3_2: Q3.2 R22.1 | length 1.6
  Top Layer 1 w0.2: Q3.2@35.123,21.091 35.123,20.839 35.279,20.683 35.378,20.683 35.71,20.351 R22.1@35.71,19.801
NetR3_2: R3.2 U1.4 | length 1.9
  Top Layer 1 w0.4: R3.2@33.705,11.566 33.905,11.366 33.905,10.83 34.152,10.584 34.152,10.013 34.217,9.947 U1.4@34.326,9.947
SEN_VMOTOR: C18.1 R11.1 R12.2 U4.25 | length 8.1
  Top Layer 1 w0.2: R11.1@3.987,18.557 4.051,18.421 4.436,17.595 4.821,16.77 4.884,16.634 5.114,16.576 5.271,16.576 5.306,16.575 5.593,16.568 5.661,16.499 7.325,14.277 7.335,14.267 7.394,14.208 U4.25@9.657,14.208
SHA: C28.2 NT2.1 R13.2 U5.37 | length 39.6
  Top Layer 1 w0.2: v1(9.217,9.177) 9.217,9.082 9.646,8.653 R13.2@9.646,8.552 ; U5.37@25.25,26.276 25.27,26.296 25.27,26.744 ; C28.2@26.393,28.231 C28.2@26.393,28.249
  Top Layer 1 w0.254: 25.27,26.744 v2@25.831,27.306
  Top Layer 1 w0.508: v2(25.847,27.461) 25.847,27.685 C28.2@26.393,28.231
  Bottom Layer w0.2: v1(9.217,9.177) 9.217,9.984 7.217,11.984 7.217,16.8 10.226,19.809 10.226,19.871 10.968,20.613 11.21,20.613 13.6,23.003 19.111,23.003 20.847,24.738 20.847,24.989 21.947,26.09 24.475,26.09 v2(25.847,27.461)
  Bottom Layer w0.508: v2(25.847,27.461) 28.899,27.461 NT2.1@30.161,28.724
SHB: C29.2 NT4.1 R15.2 U5.44 | length 33
  Top Layer 1 w0.2: v1(6.521,12.085) 6.521,12.076 7.013,11.584 R15.2@7.013,11.576 ; v2(21.556,27.318) 21.584,27.289 21.584,27.042 21.75,26.876 U5.44@21.75,26.276
  Top Layer 1 w0.381: 21.545,27.919 21.545,27.328 v2(21.556,27.318)
  Top Layer 1 w0.508: v2(20.897,30.22) 21.235,30.22 21.912,29.544 21.912,28.431 21.545,28.065 21.545,27.919
  Bottom Layer w0.2: v1(6.521,12.085) 6.521,12.12 6.803,12.402 6.803,17.667 12.992,23.855 18.276,23.855 19.594,25.173 19.594,25.432 21.405,27.243 21.451,27.243 21.526,27.318 v2(21.556,27.318)
  Bottom Layer w0.508: NT4.1@20.593,32.984 20.593,30.524 v2(20.897,30.22)
SHC: C30.2 NT6.1 R17.2 U5.47 | length 35.7
  Top Layer 1 w0.2: v1(4.568,15.358) 4.885,14.906 R17.2@4.836,14.688
  Top Layer 1 w0.254: 19.886,26.993 20.243,26.636 U5.47@20.243,26.449
  Top Layer 1 w0.381: 19.427,27.11 19.769,27.11 19.886,26.993
  Top Layer 1 w0.508: v1(17.251,27.965) 17.268,27.982 C30.2@17.911,27.982 ; C30.2@17.911,28.081 C30.2@17.911,27.982 ; 19.427,27.11 19.426,27.112 18.781,27.112 18.003,27.89 17.911,27.89 C30.2@17.911,27.982
  Bottom Layer w0.2: v1(4.568,15.358) 4.605,15.395 4.605,16.034 12.834,24.263 18.149,24.263 19.1,25.214 19.1,26.783 17.936,27.947 v1@17.268,27.947
  Bottom Layer w0.508: NT6.1@11.455,32.557 11.455,31.838 15.328,27.965 v1(17.251,27.965) v1@17.268,27.947
SLA: NT3.1 U5.40 | length 7.1
  Top Layer 1 w0.2: U5.40@23.75,26.276 23.75,26.515 v2(23.778,26.542)
  Bottom Layer w0.254: v2(23.778,26.542) 23.796,26.561 23.999,26.561 24.023,26.585
  Bottom Layer w0.381: 24.023,26.585 24.151,26.713 24.195,26.713
  Bottom Layer w0.508: 24.195,26.713 24.333,26.851 24.333,26.917 25.614,28.199 27.924,28.199 NT3.1@29.304,29.578
SLB: NT5.1 U5.41 | length 7.3
  Top Layer 1 w0.2: v2(23.163,26.737) 23.163,26.696 23.23,26.629 23.23,26.296 U5.41@23.25,26.276
  Bottom Layer w0.508: NT5.1@21.639,32.95 21.639,28.261 v2(23.163,26.737)
SLC: NT7.1 U5.2 | length 13.2
  Top Layer 1 w0.254: v2(18.368,25.159) 18.381,25.159 18.414,25.126 U5.2@19.1,25.126
  Bottom Layer w0.254: 17.775,26.848 17.913,26.848 ; v2(18.368,25.159) 18.374,25.164 18.374,26.388
  Bottom Layer w0.508: NT7.1@10.237,32.557 10.237,31.598 14.987,26.848 17.775,26.848 ; 17.913,26.848 18.374,26.388
SNA: C37.2 C38.1 R27.2 U5.4 | length 21.3
  Top Layer 1 w0.2: v2(13.983,25.575) 13.998,25.575 15.208,24.365 C38.1@15.258,24.365 C37.2@16.813,24.365 17.826,24.365 18.066,24.126 U5.4@19.1,24.126 ; v2(14.695,26.284) 14.695,29.177 15.248,29.73 19.553,29.73 22.935,33.112 R27.2@24.78,33.112
  Bottom Layer w0.2: v2(13.983,25.575) 14.692,26.284 v2(14.695,26.284)
SOA: R24.2 U5.26 | length 22.3
  Top Layer 1 w0.2: R24.2@10.432,12.027 10.451,12.046 11.044,12.046 11.184,12.187 v2(11.184,12.796) ; v2(21.525,15.481) 23.208,17.166 cw(c23.261,17.112) 23.261,17.187 23.293,17.219 25.307,17.219 25.331,17.195 25.707,17.195 25.731,17.219 26.261,17.219 26.544,17.502 26.544,20.267 26.204,20.606 25.92,20.606 U5.26@25.9,20.626
  Bottom Layer w0.2: v2(11.184,12.796) 12.828,12.796 13.376,13.344 13.962,13.344 14.481,13.863 17.13,13.863 18.304,15.036 21.093,15.036 21.525,15.468 v2(21.525,15.481)
SOB: U5.25
SOC: U5.24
